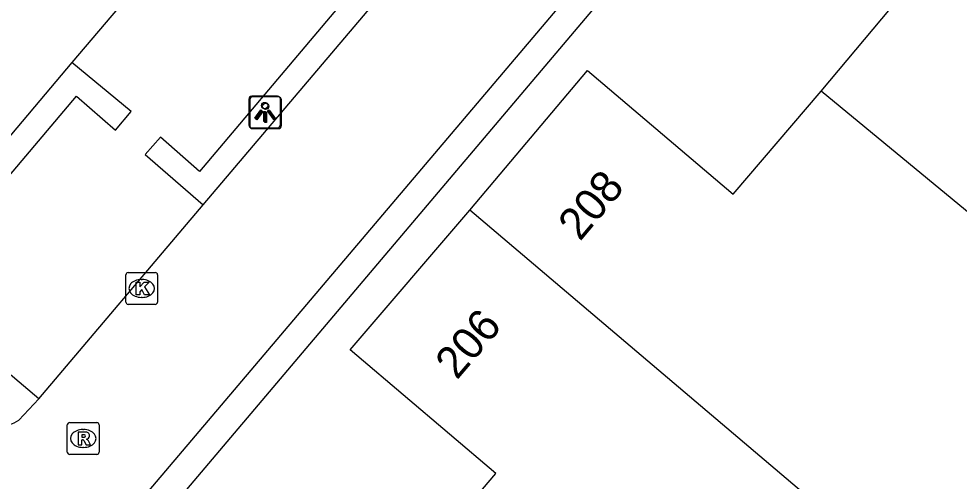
# Model space of a CAD drawing. Extents: x 156414 to 157775, y 382335 to 383765.
# Drawn here: x 157091.01 to 157120.56, y 382648.39 to 382662.91 of the extents above; entities that cross this region are included whole.
import ezdxf

# ---------------------------------------------------------------- set-up
doc = ezdxf.new("R2010")
doc.units = 0
for name, color, linetype in [('IMGEO_Kolk', 7, 'Continuous'), ('IMGEO_Lichtpunt', 7, 'Continuous'), ('IMGEO_Pand', 7, 'Continuous'), ('IMGEO_Pand_nummerreeks', 7, 'Continuous'), ('IMGEO_Parkeervlak_open', 7, 'Continuous'), ('IMGEO_Rijbaan_lokaal_open', 7, 'Continuous'), ('IMGEO_Rioolput', 7, 'Continuous'), ('IMGEO_Voetpad_open', 7, 'Continuous')]:
    doc.layers.add(name, color=color, linetype=linetype)

msp = doc.modelspace()

# ---------------------------------------------------------------- linework, layer by layer
at = {"layer": 'IMGEO_Kolk'}
for p, q in [((157094.448, 382654.941), (157095.3, 382654.941)), ((157094.373, 382654.015), (157094.373, 382654.867)), ((157094.861, 382654.721), (157094.886, 382654.721)), ((157095.374, 382654.867), (157095.374, 382654.015)), ((157094.884, 382654.161), (157094.859, 382654.161)), ((157095.3, 382653.941), (157094.448, 382653.941))]:
    msp.add_line(p, q, dxfattribs=at)
for points in [[(157094.448, 382654.941), (157095.3, 382654.941)], [(157094.373, 382654.015), (157094.373, 382654.867)], [(157094.694, 382654.641), (157094.817, 382654.641), (157094.817, 382654.49), (157094.947, 382654.641), (157095.111, 382654.641), (157094.965, 382654.49), (157095.118, 382654.241), (157094.966, 382654.241), (157094.881, 382654.405), (157094.817, 382654.338), (157094.817, 382654.241), (157094.694, 382654.241), (157094.694, 382654.641)], [(157095.374, 382654.867), (157095.374, 382654.015)], [(157095.3, 382653.941), (157094.448, 382653.941)]]:
    msp.add_lwpolyline(points, dxfattribs=at)
for centre, start, end in [((157094.45, 382654.865), 91.552, 178.448), ((157094.45, 382654.865), 91.552, 178.448), ((157095.298, 382654.865), 1.552, 88.448), ((157095.298, 382654.865), 1.552, 88.448), ((157094.45, 382654.017), 181.552, 268.448), ((157094.45, 382654.017), 181.552, 268.448), ((157095.298, 382654.017), 271.552, 358.448), ((157095.298, 382654.017), 271.552, 358.448)]:
    msp.add_arc(centre, 0.0765, start, end, dxfattribs=at)
for centre, major_axis, ratio, start_param, end_param in [((157094.86, 382654.441), (-0.387, 0.002), 0.722429, 4.712389, 7.853982), ((157094.885, 382654.441), (-0.39, 0.002), 0.717154, 1.570796, 4.712389)]:
    msp.add_ellipse(centre, major_axis=major_axis, ratio=ratio, start_param=start_param, end_param=end_param, dxfattribs=at)
at = {"layer": 'IMGEO_Lichtpunt'}
for p, q in [((157098.238, 382660.389), (157098.238, 382659.582)), ((157098.238, 382660.389), (157098.238, 382659.582)), ((157098.268, 382660.365), (157098.268, 382659.558)), ((157098.268, 382660.365), (157098.268, 382659.558)), ((157099.14, 382660.484), (157098.332, 382660.484)), ((157099.14, 382660.484), (157098.332, 382660.484)), ((157099.17, 382660.46), (157098.362, 382660.46)), ((157099.17, 382660.46), (157098.362, 382660.46)), ((157099.234, 382659.582), (157099.234, 382660.389)), ((157099.234, 382659.582), (157099.234, 382660.389)), ((157099.264, 382659.558), (157099.264, 382660.365)), ((157099.264, 382659.558), (157099.264, 382660.365)), ((157098.332, 382659.488), (157099.14, 382659.488)), ((157098.332, 382659.488), (157099.14, 382659.488)), ((157098.362, 382659.464), (157099.17, 382659.464)), ((157098.362, 382659.464), (157099.17, 382659.464))]:
    msp.add_line(p, q, dxfattribs=at)
for points in [[(157098.612, 382660.053), (157098.651, 382660.025), (157098.463, 382659.763), (157098.425, 382659.79), (157098.612, 382660.053)], [(157098.642, 382660.029), (157098.681, 382660.001), (157098.493, 382659.739), (157098.455, 382659.766), (157098.642, 382660.029)], [(157098.714, 382660.005), (157098.761, 382660.005), (157098.761, 382659.683), (157098.714, 382659.683), (157098.714, 382660.005)], [(157098.744, 382659.981), (157098.791, 382659.981), (157098.791, 382659.659), (157098.744, 382659.659), (157098.744, 382659.981)], [(157098.824, 382660.025), (157098.862, 382660.052), (157099.049, 382659.79), (157099.01, 382659.762), (157098.824, 382660.025)], [(157098.854, 382660.001), (157098.892, 382660.028), (157099.079, 382659.766), (157099.04, 382659.738), (157098.854, 382660.001)]]:
    msp.add_lwpolyline(points, dxfattribs=at)
for centre in [(157098.737, 382660.187), (157098.767, 382660.163)]:
    msp.add_circle(centre, 0.0994, dxfattribs=at)
for centre, start, end in [((157098.332, 382660.389), 90, 180), ((157098.332, 382660.389), 90, 180), ((157098.362, 382660.365), 90, 180), ((157098.362, 382660.365), 90, 180), ((157099.14, 382660.389), 0, 90), ((157099.14, 382660.389), 0, 90), ((157099.17, 382660.365), 0, 90), ((157099.17, 382660.365), 0, 90), ((157098.332, 382659.582), 180, 270), ((157098.332, 382659.582), 180, 270), ((157098.362, 382659.558), 180, 270), ((157098.362, 382659.558), 180, 270), ((157099.14, 382659.582), 270, 0), ((157099.14, 382659.582), 270, 360), ((157099.17, 382659.558), 270, 0), ((157099.17, 382659.558), 270, 360)]:
    msp.add_arc(centre, 0.0946, start, end, dxfattribs=at)
at = {"layer": 'IMGEO_Pand'}
for points in [[(157116.225, 382660.644), (157118.944, 382663.898), (157114.599, 382667.575), (157114.364, 382667.774), (157118.089, 382672.174)], [(157105.182, 382656.896), (157108.881, 382661.286), (157109.011, 382661.175), (157113.453, 382657.4), (157116.225, 382660.644)], [(157127.017, 382651.732), (157116.225, 382660.644)], [(157103.269, 382645.408), (157105.998, 382648.629), (157101.633, 382652.339), (157101.426, 382652.515), (157105.182, 382656.896)], [(157119.582, 382644.69), (157117.332, 382646.597), (157105.182, 382656.896)]]:
    msp.add_lwpolyline(points, dxfattribs=at)
at = {"layer": 'IMGEO_Parkeervlak_open'}
for points in [[(157097.943, 382667.741), (157101.939, 382664.339), (157096.688, 382658.117), (157095.466, 382659.192), (157094.985, 382658.65), (157096.802, 382657.066)], [(157091.638, 382650.975), (157087.643, 382654.359), (157092.825, 382660.479), (157094.053, 382659.418), (157094.546, 382660.003), (157092.683, 382661.545)]]:
    msp.add_lwpolyline(points, dxfattribs=at)
at = {"layer": 'IMGEO_Rijbaan_lokaal_open'}
for points in [[(157082.895, 382652.477), (157080.769, 382654.32), (157116.675, 382696.742), (157128.088, 382687.021), (157092.121, 382644.588), (157089.934, 382646.493)], [(157096.802, 382657.066), (157106.883, 382668.952)], [(157097.943, 382667.741), (157092.683, 382661.545)], [(157092.683, 382661.545), (157087.537, 382655.446), (157087.049, 382654.862), (157086.604, 382654.331), (157086.482, 382654.155)], [(157091.638, 382650.975), (157096.802, 382657.066)], [(157091.012, 382650.298), (157091.638, 382650.975)]]:
    msp.add_lwpolyline(points, dxfattribs=at)
msp.add_arc((157090.445, 382651.136), 1.012, 228.589, 304.1026, dxfattribs=at)
at = {"layer": 'IMGEO_Rioolput'}
for p, q in [((157092.611, 382650.227), (157093.463, 382650.227)), ((157092.536, 382649.301), (157092.536, 382650.153)), ((157093.024, 382650.007), (157093.049, 382650.007)), ((157093.537, 382650.153), (157093.537, 382649.301)), ((157093.047, 382649.447), (157093.022, 382649.447)), ((157093.463, 382649.227), (157092.611, 382649.227))]:
    msp.add_line(p, q, dxfattribs=at)
for points in [[(157092.611, 382650.227), (157093.463, 382650.227)], [(157092.536, 382649.301), (157092.536, 382650.153)], [(157093.125, 382649.925), (157092.873, 382649.927), (157092.873, 382649.527)], [(157093.537, 382650.153), (157093.537, 382649.301)], [(157092.873, 382649.527), (157092.997, 382649.527), (157092.997, 382649.689), (157093.008, 382649.689)], [(157093.051, 382649.846), (157092.997, 382649.846), (157092.997, 382649.765)], [(157092.997, 382649.765), (157093.049, 382649.765)], [(157093.055, 382649.66), (157093.126, 382649.527), (157093.266, 382649.527), (157093.201, 382649.653)], [(157093.463, 382649.227), (157092.611, 382649.227)]]:
    msp.add_lwpolyline(points, dxfattribs=at)
for centre, radius, start, end in [((157092.613, 382650.151), 0.0765, 91.552, 178.448), ((157092.613, 382650.151), 0.0765, 91.552, 178.448), ((157093.461, 382650.151), 0.0765, 1.552, 88.448), ((157093.461, 382650.151), 0.0765, 1.552, 88.448), ((157093.124, 382649.815), 0.109, 350.3612, 89.416), ((157093.007, 382649.636), 0.0533, 26.0293, 88.6989), ((157093.033, 382649.954), 0.19, 274.7715, 282.9687), ((157093.057, 382649.75), 0.0964, 77.0061, 93.1865), ((157093.071, 382649.807), 0.0378, 276.6634, 79.6772), ((157093.122, 382649.815), 0.112, 277.5842, 350.9817), ((157093.106, 382649.6), 0.108, 29.5134, 73.7905), ((157092.613, 382649.303), 0.0765, 181.552, 268.448), ((157092.613, 382649.303), 0.0765, 181.552, 268.448), ((157093.461, 382649.303), 0.0765, 271.552, 358.448), ((157093.461, 382649.303), 0.0765, 271.552, 358.448)]:
    msp.add_arc(centre, radius, start, end, dxfattribs=at)
for centre, major_axis, ratio, start_param, end_param in [((157093.023, 382649.727), (-0.387, 0.002), 0.722429, 4.712389, 7.853982), ((157093.048, 382649.727), (-0.39, 0.002), 0.717154, 1.570796, 4.712389)]:
    msp.add_ellipse(centre, major_axis=major_axis, ratio=ratio, start_param=start_param, end_param=end_param, dxfattribs=at)
at = {"layer": 'IMGEO_Voetpad_open'}
msp.add_lwpolyline([(157082.363, 382651.78), (157079.465, 382654.239), (157116.559, 382697.961), (157129.305, 382687.146), (157092.239, 382643.346), (157089.335, 382645.82)], dxfattribs=at)

# ---------------------------------------------------------------- texts
at = {"layer": 'IMGEO_Pand_nummerreeks'}
for s, rotation, p in [('208', 49.9791, (157108.643, 382655.899)), ('206', 49.5322, (157104.775, 382651.544))]:
    msp.add_text(s, height=1, rotation=rotation, dxfattribs=at).set_placement(p)

doc.saveas('drawing.dxf')
